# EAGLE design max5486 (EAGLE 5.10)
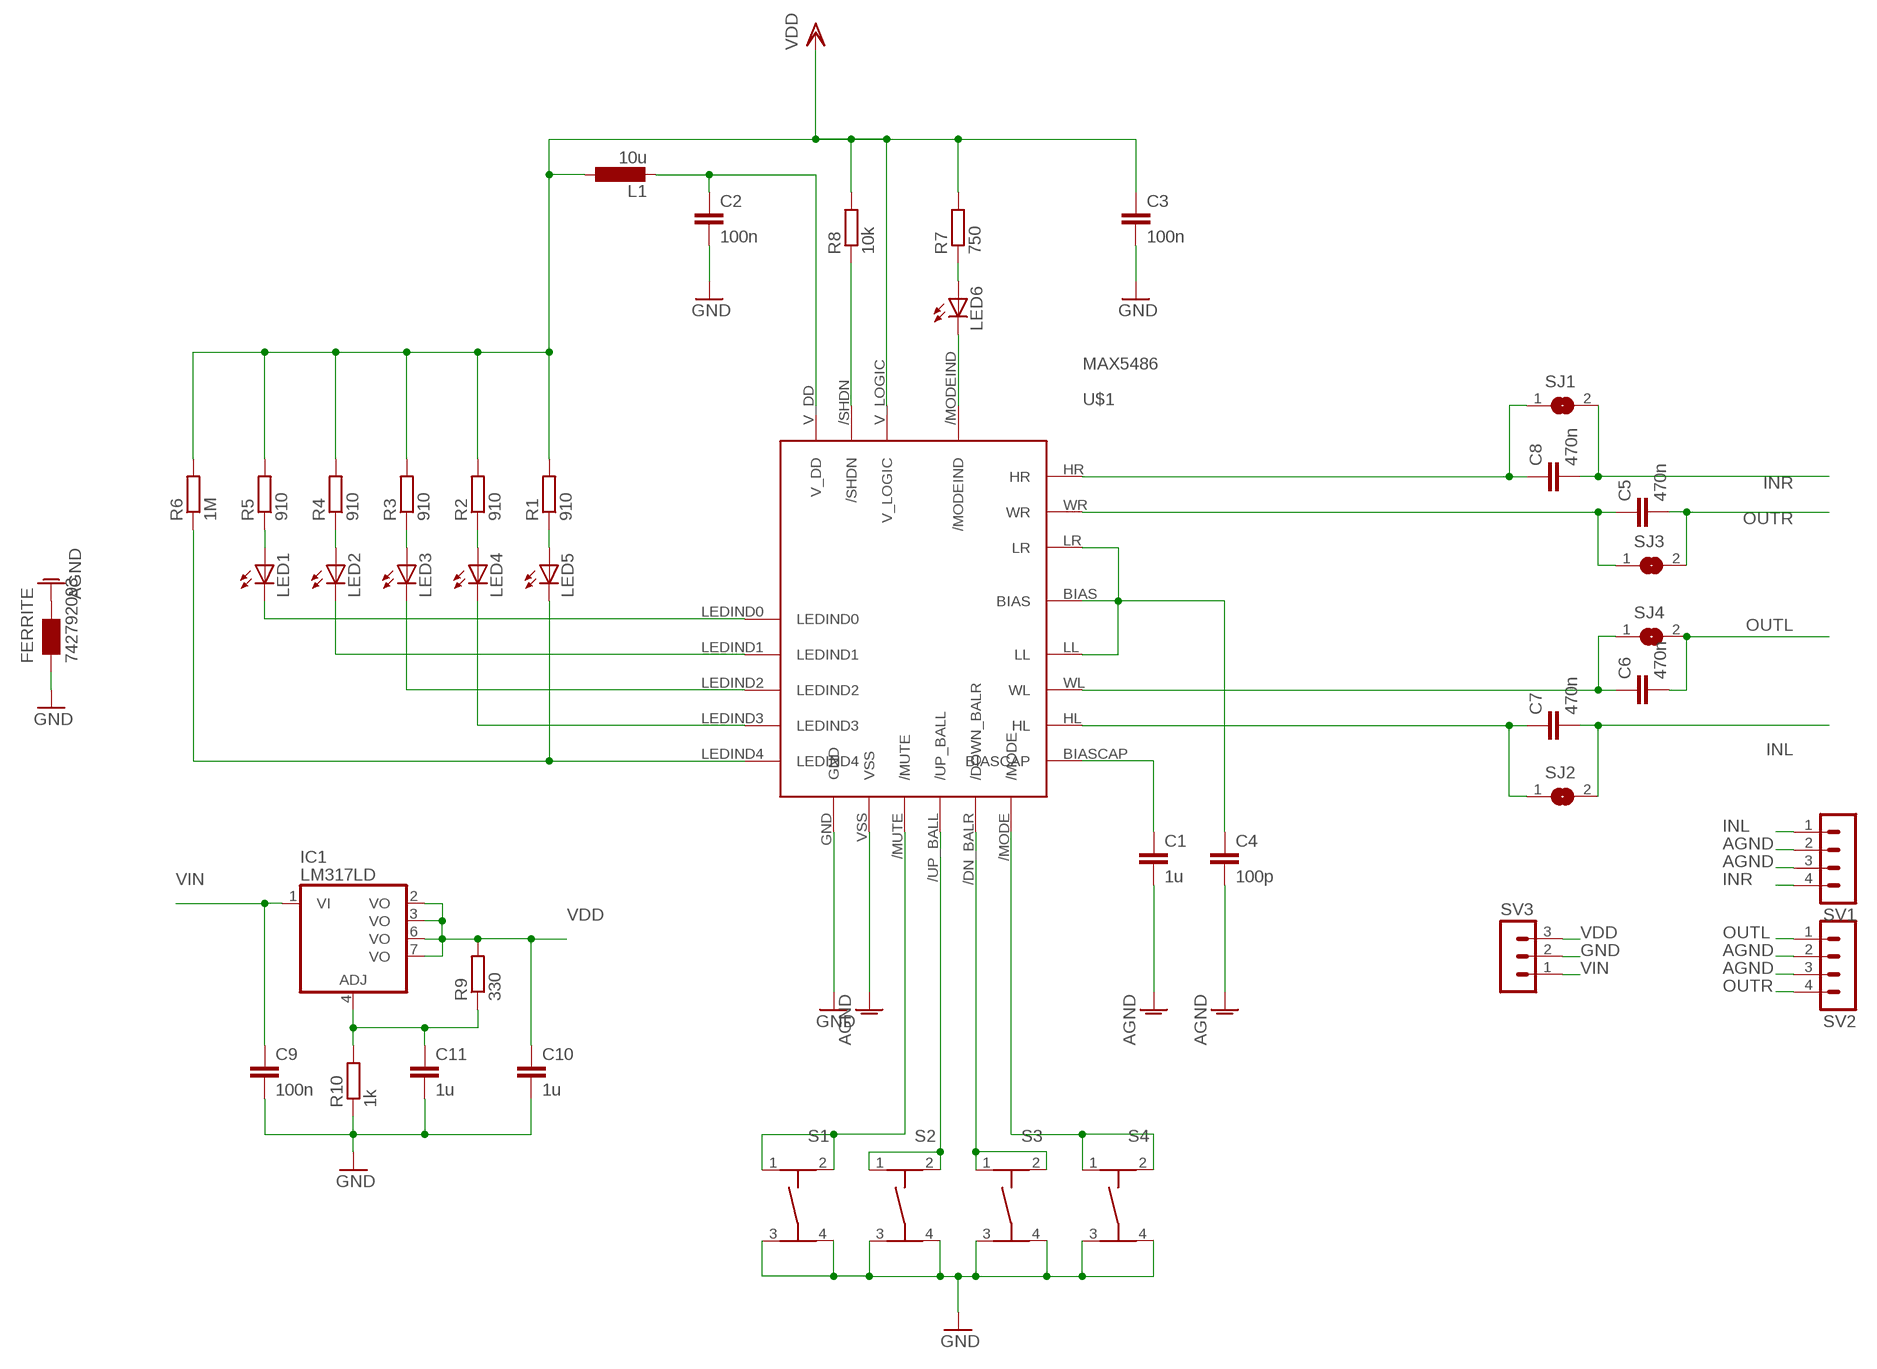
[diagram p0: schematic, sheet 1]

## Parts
C1  1u  C-EUC0805  [C0805]
C2  100n  C-EUC0805  [C0805]
C3  100n  C-EUC0805  [C0805]
C4  100p  C-EUC0805  [C0805]
C5  470n  C5/3.5  [C5B3.5]
C6  470n  C5/3.5  [C5B3.5]
C7  470n  C5/3.5  [C5B3.5]
C8  470n  C5/3.5  [C5B3.5]
C9  100n  C-EUC0805  [C0805]
C10  1u  C-EUC0805  [C0805]
C11  1u  C-EUC0805  [C0805]
FERRITE  742792093  WE-CBF_0805  [0805]
IC1  LM317LD  [SO08]
L1  10u  L-EUL1812  [L1812]
LED1  LG_T679-E1F1-1  [PLCC2]
LED2  LG_T679-E1F1-1  [PLCC2]
LED3  LG_T679-E1F1-1  [PLCC2]
LED4  LG_T679-E1F1-1  [PLCC2]
LED5  LG_T679-E1F1-1  [PLCC2]
LED6  LG_T679-E1F1-1  [PLCC2]
R1  910  R-EU_R0805  [R0805]
R2  910  R-EU_R0805  [R0805]
R3  910  R-EU_R0805  [R0805]
R4  910  R-EU_R0805  [R0805]
R5  910  R-EU_R0805  [R0805]
R6  1M  R-EU_R0805  [R0805]
R7  750  R-EU_R0805  [R0805]
R8  10k  R-EU_R0805  [R0805]
R9  330  R-EU_R0805  [R0805]
R10  1k  R-EU_R0805  [R0805]
S1  TASTER-9314_SMD  [TASTER-9314_SMD]
S2  TASTER-9314_SMD  [TASTER-9314_SMD]
S3  TASTER-9314_SMD  [TASTER-9314_SMD]
S4  TASTER-9314_SMD  [TASTER-9314_SMD]
SJ1  SJ  [SJ]
SJ2  SJ  [SJ]
SJ3  SJ  [SJ]
SJ4  SJ  [SJ]
SV1  MA04-1  [MA04-1]
SV2  MA04-1  [MA04-1]
SV3  MA03-1  [MA03-1]
U$1  MAX5486  [TSSOP24]

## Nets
AGND: C1.2 C4.2 FERRITE.2 SV1.2 SV1.3 SV2.2 SV2.3 U$1.VSS
GND: C2.2 C3.2 C9.2 C10.2 C11.2 FERRITE.1 R10.1 S1.3 S1.4 S2.3 S2.4 S3.3 S3.4 S4.3 S4.4 SV3.2 U$1.GND
INL: C7.2 SJ2.2 SV1.1
INR: C8.2 SJ1.2 SV1.4
N$1: LED5.C R6.1 U$1.LEDIND4
N$2: LED4.C U$1.LEDIND3
N$3: LED3.C U$1.LEDIND2
N$4: LED2.C U$1.LEDIND1
N$5: LED1.C U$1.LEDIND0
N$6: LED1.A R5.1
N$7: LED2.A R4.1
N$8: LED3.A R3.1
N$9: LED4.A R2.1
N$10: LED5.A R1.1
N$11: C11.1 IC1.4(ADJ) R9.1 R10.2
N$12: S2.1 S2.2 U$1./UP_BALL
N$14: S1.1 S1.2 U$1./MUTE
N$15: C4.1 U$1.BIAS U$1.LL U$1.LR
N$16: S3.1 S3.2 U$1./DN_BALR(/DOWN_BALR)
N$17: S4.1 S4.2 U$1./MODE
N$18: LED6.C U$1./MODEIND
N$19: LED6.A R7.1
N$20: C1.1 U$1.BIASCAP
N$22: R8.1 U$1./SHDN
N$23: C6.1 SJ4.1 U$1.WL
N$24: C5.1 SJ3.1 U$1.WR
N$25: C2.1 L1.2 U$1.V_DD
N$27: C7.1 SJ2.1 U$1.HL
N$28: C8.1 SJ1.1 U$1.HR
OUTL: C6.2 SJ4.2 SV2.1
OUTR: C5.2 SJ3.2 SV2.4
VDD: C3.1 C10.1 IC1.2(VO) IC1.3(VO) IC1.6(VO) IC1.7(VO) L1.1 R1.2 R2.2 R3.2 R4.2 R5.2 R6.2 R7.2 R8.2 R9.2 SV3.3 U$1.V_LOGIC
VIN: C9.1 IC1.1(VI) SV3.1

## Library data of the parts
C1 C4 C10 C11 = rcl:C-EU: CAPACITOR, European symbol
C2 C3 C9 = resistor:C-EU: CAPACITOR, European symbol
C5-C8 = capacitor-wima:C: CAPACITOR
FERRITE = wuerth-elektronik:WE-CBF: SMD EMI Suppression Ferrite Beads
IC1 = linear:LM317LD: LOW CURRENT 1.2 TO 37V ADJUSTABLE VOLTAGE REGULATOR Source: http://pdf.alldatasheet.com
L1 = rcl:L-EU: INDUCTOR, European symbol
LED1-LED6 = led:*_T679-?-1: LC TOPLED® Low Current LED; COLOR: green
R1-R10 = rcl:R-EU_: RESISTOR, European symbol
S1-S4 = SMD_Switches:TASTER-9314_SMD
SJ1-SJ4 = jumper:SJ: SMD solder JUMPER
SV1 SV2 = con-lstb:MA04-1: PIN HEADER
SV3 = con-lstb:MA03-1: PIN HEADER
U$1 = maxim-ic2:MAX5486: MAX5486 TSSOP24

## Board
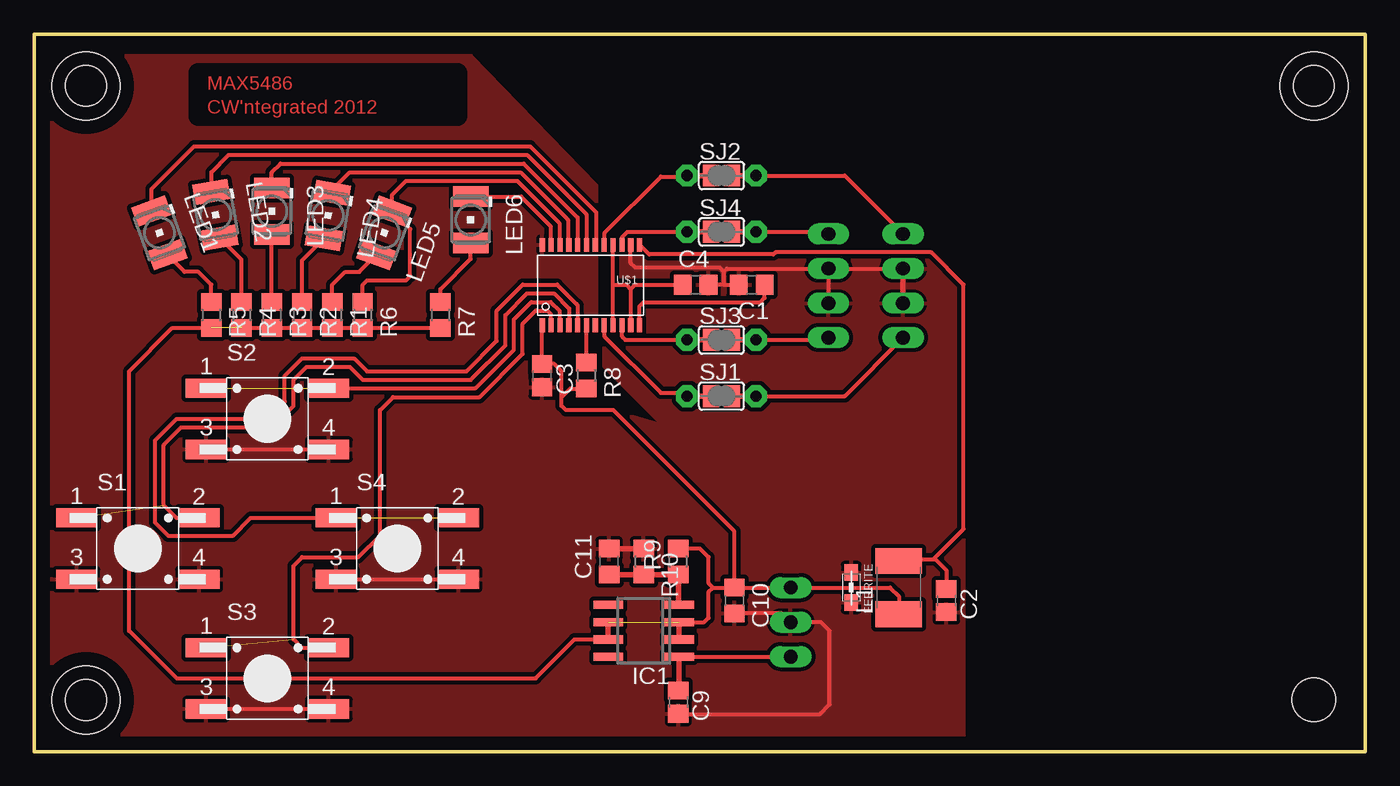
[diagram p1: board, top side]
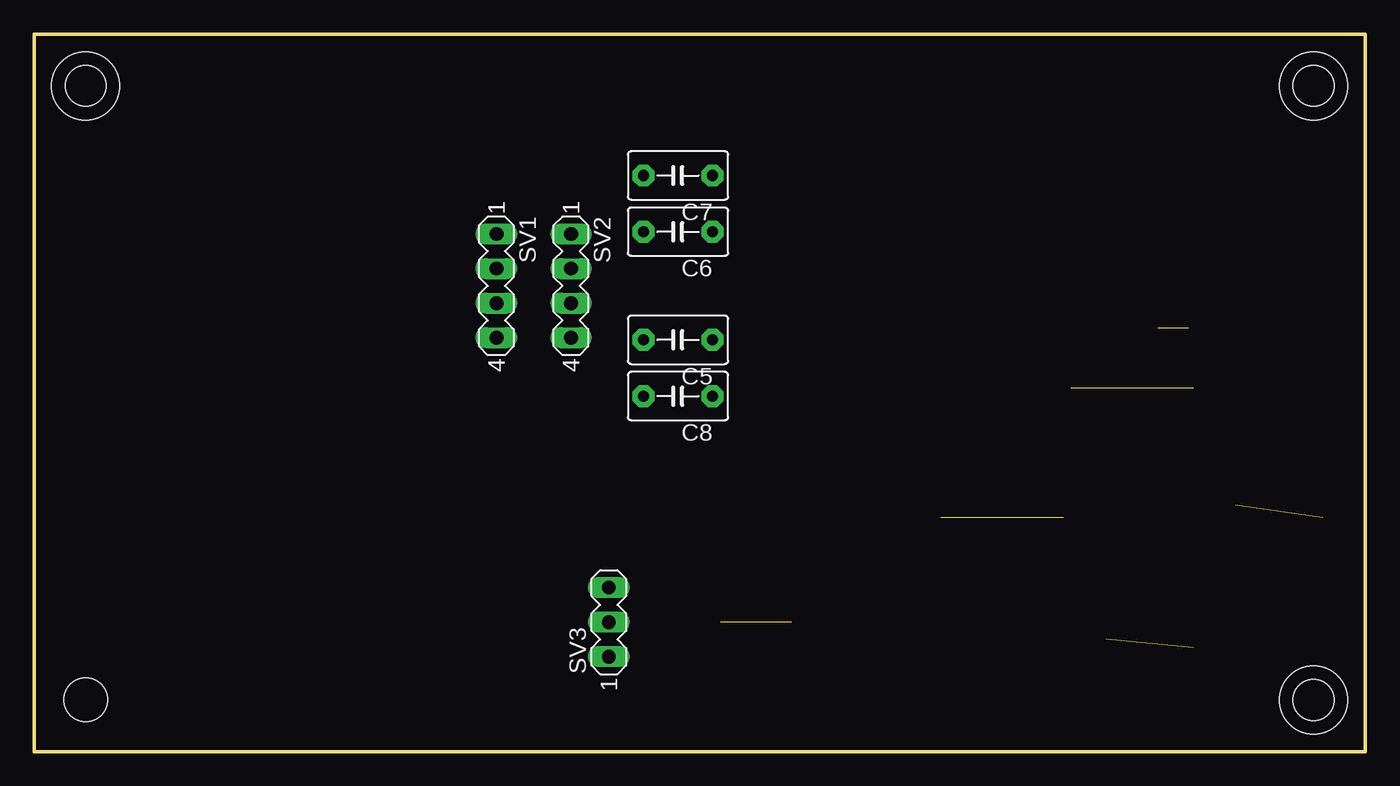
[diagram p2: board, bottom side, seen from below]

Size 97.77 x 52.69 mm. Coordinates in mm from the lower left corner, seen from the top.
Outline: 0,0 97.77,0 97.77,52.69 0,52.69 0,0
Copper layers (1*16): Top 0.035mm / dielectric 1.5mm / Bottom 0.035mm
Design rules "default": minimum track width 10mil, minimum drill 24mil, track to track 8mil, track to pad 8mil, pad to pad 8mil, via to via 8mil, smd to smd 8mil, copper to edge 40mil, drill to drill 8mil, minimum pad ring 10mil, minimum via ring 8mil, stop-mask expansion 4mil, vias tented up to drill 0mil, thermal gap 10mil
Holes 3.2 mm at 93.98,3.81
Holes 3 mm at 3.81,3.81 3.81,48.89 93.98,48.89
Holes 5 mm at 3.81,48.89 93.98,48.89 3.81,3.81
tRestrict: area 12.1,46.7 to 31.1,49.8

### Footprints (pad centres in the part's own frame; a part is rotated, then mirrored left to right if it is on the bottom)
C0805 = smd 1.3 x 1.5: 1 -0.95,0; 2 0.95,0
C0805' = smd 1.3 x 1.5: 1 -0.85,0; 2 0.85,0
C5B3.5 = drill 0.813 pad 1.6 octagon: 1 -2.54,0; 2 2.54,0
0805 = smd 1.2 x 1: 1 -1.1,0; 2 1.1,0
SO08 = smd 0.6 x 2.2: 1 -1.905,-2.6; 2 -0.635,-2.6; 3 0.635,-2.6; 4 1.905,-2.6; 5 1.905,2.6; 6 0.635,2.6; 7 -0.635,2.6; 8 -1.905,2.6
L1812 = smd 1.9 x 3.4: 1 -1.95,0; 2 1.95,0
PLCC2 = smd 2.6 x 1.5: A 0,1.7; C 0,-1.7
R0805 = smd 1.3 x 1.5: 1 -0.95,0; 2 0.95,0
TASTER-9314_SMD = smd 3 x 1.4: 1 -4.5,2.25; 2 4.5,2.25; 3 -4.5,-2.25; 4 4.5,-2.25
SJ = smd 1.168 x 1.6: 1 -0.762,0; 2 0.762,0
MA04-1 = drill 1.016 long: 1 -3.81,0; 2 -1.27,0; 3 1.27,0; 4 3.81,0
MA03-1 = drill 1.016 long: 1 -2.54,0; 2 0,0; 3 2.54,0
TSSOP24 = smd 1 x 0.38: /DN_BALR -0.75,6.8; /MODE -0.75,4.85; /MODEIND 5.15,6.8; /MUTE -0.75,5.5; /SHDN -0.75,4.2; /UP_BALL -0.75,6.15; BIAS -0.75,0.95; BIASCAP -0.75,0.3; GND 5.15,7.45; HL 5.15,2.9; HR -0.75,2.9; LEDIND0 5.15,3.55; LEDIND1 5.15,4.2; LEDIND2 5.15,4.85; LEDIND3 5.15,5.5; LEDIND4 5.15,6.15; LL 5.15,2.25; LR -0.75,2.25; N.C. -0.75,3.55; V_DD 5.15,0.3; V_LOGIC -0.75,7.45; VSS 5.15,0.95; WL 5.15,1.6; WR -0.75,1.6

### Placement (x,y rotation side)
C1  52.7,34.29 180 top
C2  100n  [C0805']  66.99,11.11 270 top
C3  100n  [C0805']  37.31,27.62 270 top
C4  48.58,34.29 0 top
C5  50.48,30.24 180 bottom
C6  50.48,38.18 180 bottom
C7  50.48,42.31 180 bottom
C8  50.48,26.11 180 bottom
C9  100n  [C0805']  47.31,3.65 270 top
C10  51.43,11.11 270 top
C11  42.23,13.97 90 top
FERRITE  60.01,12.06 90 top
IC1  44.77,8.89 90 top
L1  63.5,12.06 90 top
LED1  9.21,38.1 200 top
LED2  13.33,39.43 190 top
LED3  17.46,39.69 180 top
LED4  21.59,39.37 170 top
LED5  25.72,38.1 160 top
LED6  32.07,39.05 180 top
R1  21.91,32.07 270 top
R2  19.69,32.07 270 top
R3  17.46,32.07 270 top
R4  15.24,32.07 270 top
R5  13.02,32.07 270 top
R6  24.13,32.07 270 top
R7  29.85,32.07 270 top
R8  40.56,27.62 270 top
R9  47.31,13.97 90 top
R10  44.77,13.97 270 top
S1  7.62,14.92 0 top
S2  17.15,24.45 0 top
S3  17.15,5.4 0 top
S4  26.67,14.92 0 top
SJ1  50.48,26.11 0 top
SJ2  50.48,42.31 0 top
SJ3  50.48,30.24 0 top
SJ4  50.48,38.18 0 top
SV1  63.82,34.21 270 bottom
SV2  58.34,34.21 270 bottom
SV3  55.56,9.53 90 bottom
U$1  44.77,32.07 90 top

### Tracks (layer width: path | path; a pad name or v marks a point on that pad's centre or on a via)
AGND
  Top 0.305: 50.64,34.29 C4.2 | 50.64,34.29 C1.2 | SV2.2 SV2.3 | 50.64,35.24 50.88,35.48 SV2.2 | 50.64,35.24 50.64,34.29 | U$1.VSS 43.82,35.88 44.13,35.56 50.32,35.56 50.64,35.24 | SV2.2 SV1.2
  Top 0.406: SV1.2 SV1.3
  pour Top (isolate 0.305): 58.74,12.06 58.74,15.56 53.34,20.96 49.21,20.96 41.91,28.26 41.91,41.59 45.72,45.4 68.26,45.4 68.26,12.06
GND
  Top 0.305: S4.3 S4.4 | S3.3 S3.4 | S2.3 S2.4 | C9.2 47.33,2.78 57.71,2.78 58.42,3.49 58.42,8.89 57.78,9.53 SV3.2 54.92,10.16 C10.2
  Top 0.406: C11.2 R10.1
  pour Top (isolate 0.305): 0,0 0,51.12 32.07,51.12 41.27,41.59 41.27,25.4 68.26,17.46 68.26,0
INL
  Top 0.305: C7.2 59.53,42.31 SV1.1
  Top 0.406: SJ2.2 C7.2
INR
  Top 0.305: C8.2 59.53,26.11 SV1.4
  Top 0.406: SJ1.2 C8.2
N$1
  Top 0.305: U$1.LEDIND4 38.58,37.26 38.58,38.81 35.48,41.91 27.31,41.91 26.3,40.9 LED5.C 27.62,38.37 27.62,34.92 27.31,34.61 24.45,34.61 24.13,34.29 R6.1
N$2
  Top 0.305: LED4.C 21.89,41.25 23.18,42.54 35.72,42.54 39.21,39.05 39.21,37.27 U$1.LEDIND3
N$3
  Top 0.305: LED3.C 17.46,42.54 18.1,43.18 35.96,43.18 39.93,39.21 39.93,37.23 U$1.LEDIND2
N$4
  Top 0.305: LED2.C 13.04,42.56 14.29,43.81 36.2,43.81 40.56,39.45 U$1.LEDIND1
N$5
  Top 0.305: LED1.C 8.63,41.33 11.75,44.45 36.43,44.45 41.27,39.61 41.27,37.27 U$1.LEDIND0
N$6
  Top 0.305: R5.1 13.02,34.29 12.06,35.24 11.05,35.24 LED1.A
N$7
  Top 0.305: R4.1 15.24,36.14 LED2.A
N$8
  Top 0.305: R3.1 LED3.A
N$9
  Top 0.305: R2.1 19.69,36.09 LED4.A
N$10
  Top 0.305: R1.1 21.91,34.29 22.86,35.24 23.88,35.24 LED5.A
N$11
  Top 0.406: C11.1 R10.2 R9.1 47.31,10.86 IC1.4
N$12  (1 unrouted)
  Top 0.305: S2.2 32.41,26.7 35.24,29.53 35.24,31.75 36.51,33.02 37.94,33.02 38.58,32.38 38.58,31.36 U$1./UP_BALL
N$14  (1 unrouted)
  Top 0.305: S1.2 10.45,17.17 9.53,18.1 9.53,22.54 10.79,23.81 17.46,23.81 19.05,25.4 19.05,27.31 20,28.26 23.18,28.26 24.13,27.31 32.07,27.31 34.61,29.85 34.61,32.07 36.2,33.66 38.18,33.66 39.29,32.54 39.29,31.34 U$1./MUTE
N$15
  Top 0.305: U$1.LR 42.52,34.29 | 42.52,34.29 U$1.LL | 43.82,33.97 U$1.BIAS | 43.82,33.97 43.5,34.29 42.52,34.29 | C4.1 44.14,34.29 43.82,33.97
N$16  (1 unrouted)
  Top 0.305: S3.2 19.66,7.65 19.05,8.26 19.05,13.65 19.69,14.29 23.81,14.29 25.4,15.88 25.4,25.08 26.35,26.04 32.7,26.04 35.88,29.21 35.88,31.43 36.83,32.38 37.7,32.38 37.94,32.15 37.94,31.34 U$1./DN_BALR
N$17  (1 unrouted)
  Top 0.305: S4.1 15.9,17.17 14.61,15.88 9.84,15.88 8.89,16.83 8.89,22.86 10.48,24.45 17.15,24.45 18.42,25.72 18.42,27.62 19.69,28.89 23.5,28.89 24.45,27.94 31.75,27.94 33.97,30.16 33.97,32.38 35.88,34.29 38.42,34.29 39.85,32.86 | 39.85,32.86 | 39.85,32.86 39.93,32.78 U$1./MODE
N$18
  Top 0.305: LED6.C 35.77,40.75 37.94,38.58 37.94,37.24 U$1./MODEIND
N$19
  Top 0.305: R7.1 29.85,33.97 32.07,36.2 LED6.A
N$20
  Top 0.305: C1.1 53.66,33.34 53.34,33.02 44.77,33.02 44.45,32.7 44.45,31.34 U$1.BIASCAP
N$22
  Top 0.305: R8.1 U$1./SHDN
N$23
  Top 0.305: C6.1 43.58,38.18 43.18,37.78 43.18,37.23 U$1.WL
  Top 0.406: C6.1 SJ4.1
N$24
  Top 0.305: C5.1 43.42,30.24 43.18,30.48 43.18,31.31 U$1.WR
  Top 0.406: C5.1 SJ3.1
N$25
  Top 0.305: C2.1 66.99,13.33 66.2,14.13 66.04,14.13 | 66.04,14.13 63.61,14.13 L1.2 | U$1.V_DD 45.17,36.51 54.29,36.51 54.45,36.67 65.88,36.67 68.26,34.29 68.26,16.35 66.04,14.13
N$27
  Top 0.305: U$1.HL 41.91,37.26 41.91,38.1 46.04,42.23 47.86,42.23 C7.1
  Top 0.406: C7.1 SJ2.1
N$28
  Top 0.305: U$1.HR 41.91,31.28 41.91,30.48 46.04,26.35 47.7,26.35 C8.1
  Top 0.406: C8.1 SJ1.1
OUTL
  Top 0.305: C6.2 58.18,38.18 SV2.1
  Top 0.406: SJ4.2 C6.2
OUTR
  Top 0.305: C5.2 58.18,30.24 SV2.4
  Top 0.406: SJ3.2 C5.2
VDD  (2 unrouted)
  Top 0.305: C10.1 SV3.3 62.86,12.06 63.5,11.43 L1.1 | IC1.3 49.21,9.53 49.53,9.84 49.53,11.75 49.85,12.06 | 49.85,12.06 C10.1 | R4.2 R3.2 R2.2 R1.2 R6.2 R7.2 | U$1.V_LOGIC C3.1 38.2,28.47 38.73,27.94 38.73,26.04 | C10.1 51.43,16.19 42.54,25.08 39.05,25.08 38.73,25.4 38.73,26.04 | R9.2 48.9,14.92 49.53,14.29 49.53,12.38 49.85,12.06 | R8.2 39.37,26.67 38.73,26.04 | R5.2 10.16,31.12 6.98,27.94 6.98,8.89 10.48,5.4 36.83,5.4 39.69,8.26 IC1.7
  Top 0.406: IC1.7 IC1.6 | IC1.3 IC1.2
VIN
  Top 0.305: IC1.1 SV3.1
  Top 0.406: IC1.1 47.37,4.56 C9.1

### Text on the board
Top: MAX5486 | CW'ntegrated 2012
